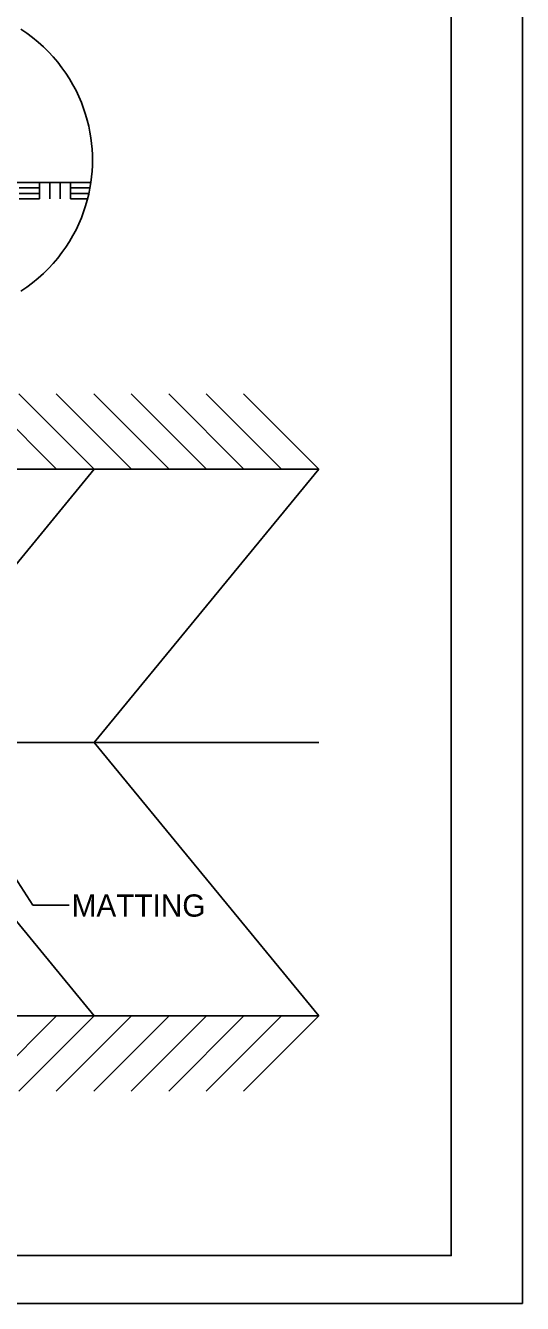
# Model space of a CAD drawing. Extents: x 8096 to 9796, y 9620 to 10720.
# Drawn here: x 9562 to 9796, y 9620 to 10220 of the extents above; entities that cross this region are included whole.
import ezdxf

# ---------------------------------------------------------------- set-up
doc = ezdxf.new("R2010")
doc.units = 0
for name, color, linetype in [('Blank Plan Sheet Both CELL', 7, 'Continuous'), ('Default', 7, 'Continuous'), ('Old_Level_1', 7, 'Continuous'), ('Old_Level_2', 7, 'Continuous'), ('Sheet Plot Border Outside CELL', 7, 'Continuous')]:
    doc.layers.add(name, color=color, linetype=linetype)

msp = doc.modelspace()

# ---------------------------------------------------------------- linework, layer by layer
at = {"layer": 'Blank Plan Sheet Both CELL'}
msp.add_lwpolyline([(9762.02, 10692.33), (8262.02, 10692.33), (8262.02, 9642.33), (9762.02, 9642.33)], close=True, dxfattribs=at)
at = {"layer": 'Default'}
for p, q in [((9576.53, 10011.98), (9541.18, 10047.33)), ((9594.14, 10011.98), (9558.79, 10047.33)), ((9611.75, 10011.98), (9576.39, 10047.33)), ((9629.36, 10011.98), (9594, 10047.33)), ((9646.97, 10011.98), (9611.61, 10047.33)), ((9664.57, 10011.98), (9629.22, 10047.33)), ((9682.18, 10011.98), (9646.83, 10047.33)), ((9699.79, 10011.98), (9664.44, 10047.33)), ((9576.53, 9754.98), (9541.18, 9719.62)), ((9594.14, 9754.98), (9558.79, 9719.62)), ((9611.75, 9754.98), (9576.39, 9719.62)), ((9629.36, 9754.98), (9594, 9719.62)), ((9646.97, 9754.98), (9611.61, 9719.62)), ((9664.57, 9754.98), (9629.22, 9719.62)), ((9682.18, 9754.98), (9646.83, 9719.62)), ((9699.79, 9754.98), (9664.44, 9719.62))]:
    msp.add_line(p, q, dxfattribs=at)
for points in [[(9562.53, 10216.83), (9559.73, 10218.72)], [(9565.23, 10214.83), (9562.53, 10216.83)], [(9567.82, 10212.71), (9565.23, 10214.83)], [(9570.31, 10210.48), (9567.82, 10212.71)], [(9572.68, 10208.15), (9570.31, 10210.48)], [(9574.93, 10205.74), (9572.68, 10208.15)], [(9577.05, 10203.24), (9574.93, 10205.74)], [(9579.04, 10200.67), (9577.05, 10203.24)], [(9580.9, 10198.05), (9579.04, 10200.67)], [(9582.62, 10195.37), (9580.9, 10198.05)], [(9584.21, 10192.64), (9582.62, 10195.37)], [(9585.66, 10189.89), (9584.21, 10192.64)], [(9586.98, 10187.11), (9585.66, 10189.89)], [(9588.16, 10184.32), (9586.98, 10187.11)], [(9589.22, 10181.52), (9588.16, 10184.32)], [(9590.14, 10178.72), (9589.22, 10181.52)], [(9590.94, 10175.93), (9590.14, 10178.72)], [(9591.62, 10173.16), (9590.94, 10175.93)], [(9592.18, 10170.41), (9591.62, 10173.16)], [(9592.62, 10167.69), (9592.18, 10170.41)], [(9592.96, 10165), (9592.62, 10167.69)], [(9593.2, 10162.36), (9592.96, 10165)], [(9593.34, 10159.76), (9593.2, 10162.36)], [(9593.38, 10157.2), (9593.34, 10159.76)], [(9593.34, 10154.64), (9593.38, 10157.2)], [(9592.96, 10149.4), (9593.2, 10152.04)], [(9593.2, 10152.04), (9593.34, 10154.64)], [(9592.18, 10143.99), (9592.62, 10146.71)], [(9592.62, 10146.71), (9592.96, 10149.4)], [(9590.94, 10138.47), (9591.62, 10141.24)], [(9591.62, 10141.24), (9592.18, 10143.99)], [(9588.16, 10130.08), (9589.22, 10132.88)], [(9589.22, 10132.88), (9590.14, 10135.68)], [(9590.14, 10135.68), (9590.94, 10138.47)], [(9585.66, 10124.51), (9586.98, 10127.29)], [(9586.98, 10127.29), (9588.16, 10130.08)], [(9582.62, 10119.03), (9584.21, 10121.76)], [(9584.21, 10121.76), (9585.66, 10124.51)], [(9579.04, 10113.73), (9580.9, 10116.35)], [(9580.9, 10116.35), (9582.62, 10119.03)], [(9574.93, 10108.66), (9577.05, 10111.16)], [(9577.05, 10111.16), (9579.04, 10113.73)], [(9567.82, 10101.69), (9570.31, 10103.92)], [(9570.31, 10103.92), (9572.68, 10106.25)], [(9572.68, 10106.25), (9574.93, 10108.66)], [(9559.73, 10095.68), (9562.53, 10097.57)], [(9562.53, 10097.57), (9565.23, 10099.57)], [(9565.23, 10099.57), (9567.82, 10101.69)], [(9594.14, 10011.98), (9533.77, 9938.55)], [(9699.79, 10011.98), (9594.14, 9883.48), (9699.79, 9754.98)], [(9533.77, 9828.41), (9594.14, 9754.98)]]:
    msp.add_lwpolyline(points, dxfattribs=at)
at = {"layer": 'Old_Level_1'}
for p, q in [((9448.03, 10146.67), (9592.62, 10146.67)), ((9568.52, 10139.04), (9568.52, 10146.67)), ((9573.34, 10139.04), (9573.34, 10146.67)), ((9578.16, 10139.04), (9578.16, 10146.67)), ((9582.98, 10139.04), (9582.98, 10146.67)), ((9412.86, 10011.98), (9699.79, 10011.98)), ((9412.86, 9883.48), (9699.79, 9883.48)), ((9565.31, 9807.04), (9533.77, 9855.94)), ((9565.31, 9807.04), (9582.44, 9807.04)), ((9412.86, 9754.98), (9699.79, 9754.98))]:
    msp.add_line(p, q, dxfattribs=at)
for points in [[(9558.88, 10144.13), (9568.52, 10144.13)], [(9558.88, 10141.58), (9568.52, 10141.58)], [(9558.88, 10139.04), (9568.52, 10139.04)], [(9582.66, 10144.13), (9592.2, 10144.13)], [(9582.98, 10141.58), (9591.69, 10141.58)], [(9582.98, 10139.04), (9591.08, 10139.04)]]:
    msp.add_lwpolyline(points, dxfattribs=at)
at = {"layer": 'Sheet Plot Border Outside CELL'}
msp.add_lwpolyline([(8095.52, 9619.83), (9795.52, 9619.83), (9795.52, 10719.83), (8095.52, 10719.83)], close=True, dxfattribs=at)

# ---------------------------------------------------------------- texts
at = {"layer": 'Old_Level_2'}
msp.add_text('MATTING', height=10.454, dxfattribs=at).set_placement((9583.59, 9801.64))

doc.saveas('drawing.dxf')
